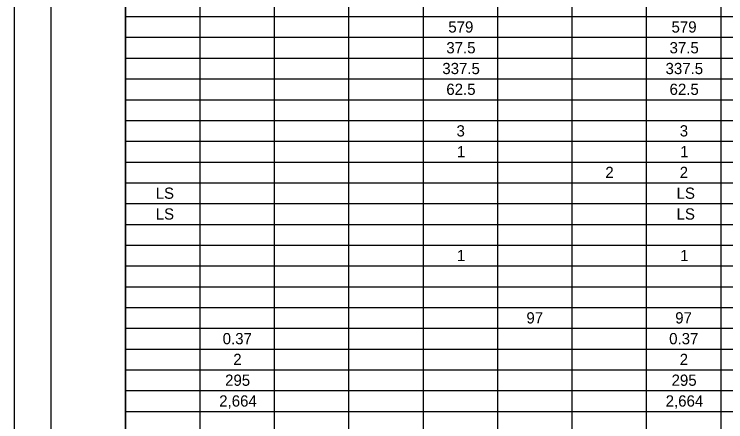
# Model space of a CAD drawing. Extents: x 0 to 34, y 0 to 22.
# Drawn here: x 0 to 9.6, y 11 to 16.49 of the extents above; entities that cross this region are included whole.
import ezdxf

# ---------------------------------------------------------------- set-up
doc = ezdxf.new("R2010")
doc.units = 0
for name, color, linetype in [('Default', 7, 'Continuous'), ('SH_Border', 7, 'Continuous'), ('SH_Cut_Line', 7, 'Continuous')]:
    doc.layers.add(name, color=color, linetype=linetype)

msp = doc.modelspace()

# ---------------------------------------------------------------- linework, layer by layer
at = {"layer": 'Default'}
for p, q in [((1.5, 21.5), (1.5, 0.5)), ((8.5283, 21.5), (8.5283, 0.5)), ((9.5324, 21.5), (9.5324, 0.5)), ((2.504, 20.94), (2.504, 0.5)), ((3.5081, 20.94), (3.5081, 0.5)), ((4.5121, 20.94), (4.5121, 0.5)), ((5.5162, 20.94), (5.5162, 0.5)), ((6.5202, 20.94), (6.5202, 0.5)), ((7.5243, 20.94), (7.5243, 0.5)), ((1.5, 16.46), (32, 16.46)), ((1.5, 16.18), (32, 16.18)), ((1.5, 15.9), (32, 15.9)), ((1.5, 15.62), (32, 15.62)), ((1.5, 15.34), (32, 15.34)), ((1.5, 15.06), (32, 15.06)), ((1.5, 14.78), (32, 14.78)), ((1.5, 14.5), (32, 14.5)), ((1.5, 14.22), (32, 14.22)), ((1.5, 13.94), (32, 13.94)), ((1.5, 13.66), (32, 13.66)), ((1.5, 13.38), (32, 13.38)), ((1.5, 13.1), (32, 13.1)), ((1.5, 12.82), (32, 12.82)), ((1.5, 12.54), (32, 12.54)), ((1.5, 12.26), (32, 12.26)), ((1.5, 11.98), (32, 11.98)), ((1.5, 11.7), (32, 11.7)), ((1.5, 11.42), (32, 11.42)), ((1.5, 11.14), (32, 11.14))]:
    msp.add_line(p, q, dxfattribs=at)
at = {"layer": 'SH_Border'}
for points in [[(0.5, 21.5), (1.5, 21.5), (1.5, 0.5), (0.5, 0.5)], [(1.5, 21.5), (33.5, 21.5), (33.5, 0.5), (1.5, 0.5)]]:
    msp.add_lwpolyline(points, close=True, dxfattribs=at)
at = {"layer": 'SH_Cut_Line'}
msp.add_lwpolyline([(0, 0), (34, 0), (34, 22), (0, 22)], close=True, dxfattribs=at)

# ---------------------------------------------------------------- texts
at = {"layer": 'Default'}
for s, height, p in [('579', 0.15153, (5.8567, 16.2442)), ('579', 0.15153, (8.8688, 16.2442)), ('37.5', 0.15153, (5.8302, 15.9642)), ('37.5', 0.15153, (8.8424, 15.9642)), ('337.5', 0.15153, (5.7758, 15.6842)), ('337.5', 0.15153, (8.788, 15.6842)), ('62.5', 0.15153, (5.8302, 15.4042)), ('62.5', 0.15153, (8.8424, 15.4042)), ('3', 0.1515, (5.9677, 14.8442)), ('3', 0.1515, (8.9799, 14.8442)), ('1', 0.1515, (5.9736, 14.5642)), ('1', 0.1515, (8.9858, 14.5642)), ('2', 0.1515, (7.9754, 14.2842)), ('2', 0.1515, (8.9795, 14.2842)), ('LS', 0.15153, (1.9087, 14.0042)), ('LS', 0.15153, (8.937, 14.0042)), ('LS', 0.15153, (1.9087, 13.7242)), ('LS', 0.15153, (8.937, 13.7242)), ('1', 0.1515, (5.9736, 13.1642)), ('1', 0.1515, (8.9858, 13.1642)), ('97', 0.15153, (6.9104, 12.3242)), ('97', 0.15153, (8.9184, 12.3242)), ('0.37', 0.15153, (2.8126, 12.0442)), ('0.37', 0.15153, (8.8369, 12.0442)), ('2', 0.1515, (2.9552, 11.7642)), ('2', 0.1515, (8.9795, 11.7642)), ('295', 0.15153, (2.8452, 11.4842)), ('295', 0.15153, (8.8695, 11.4842)), ('2,664', 0.15153, (2.7656, 11.2042)), ('2,664', 0.15153, (8.7899, 11.2042))]:
    msp.add_text(s, height=height, dxfattribs=at).set_placement(p)

doc.saveas('drawing.dxf')
